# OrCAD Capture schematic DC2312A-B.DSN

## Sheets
1 PAGE3: size B; title: HIGH EFFICIENCY  DC/DC CONVERTER WITH POWER SYSTEM MANAGEMENT; rev: 2; company: TM
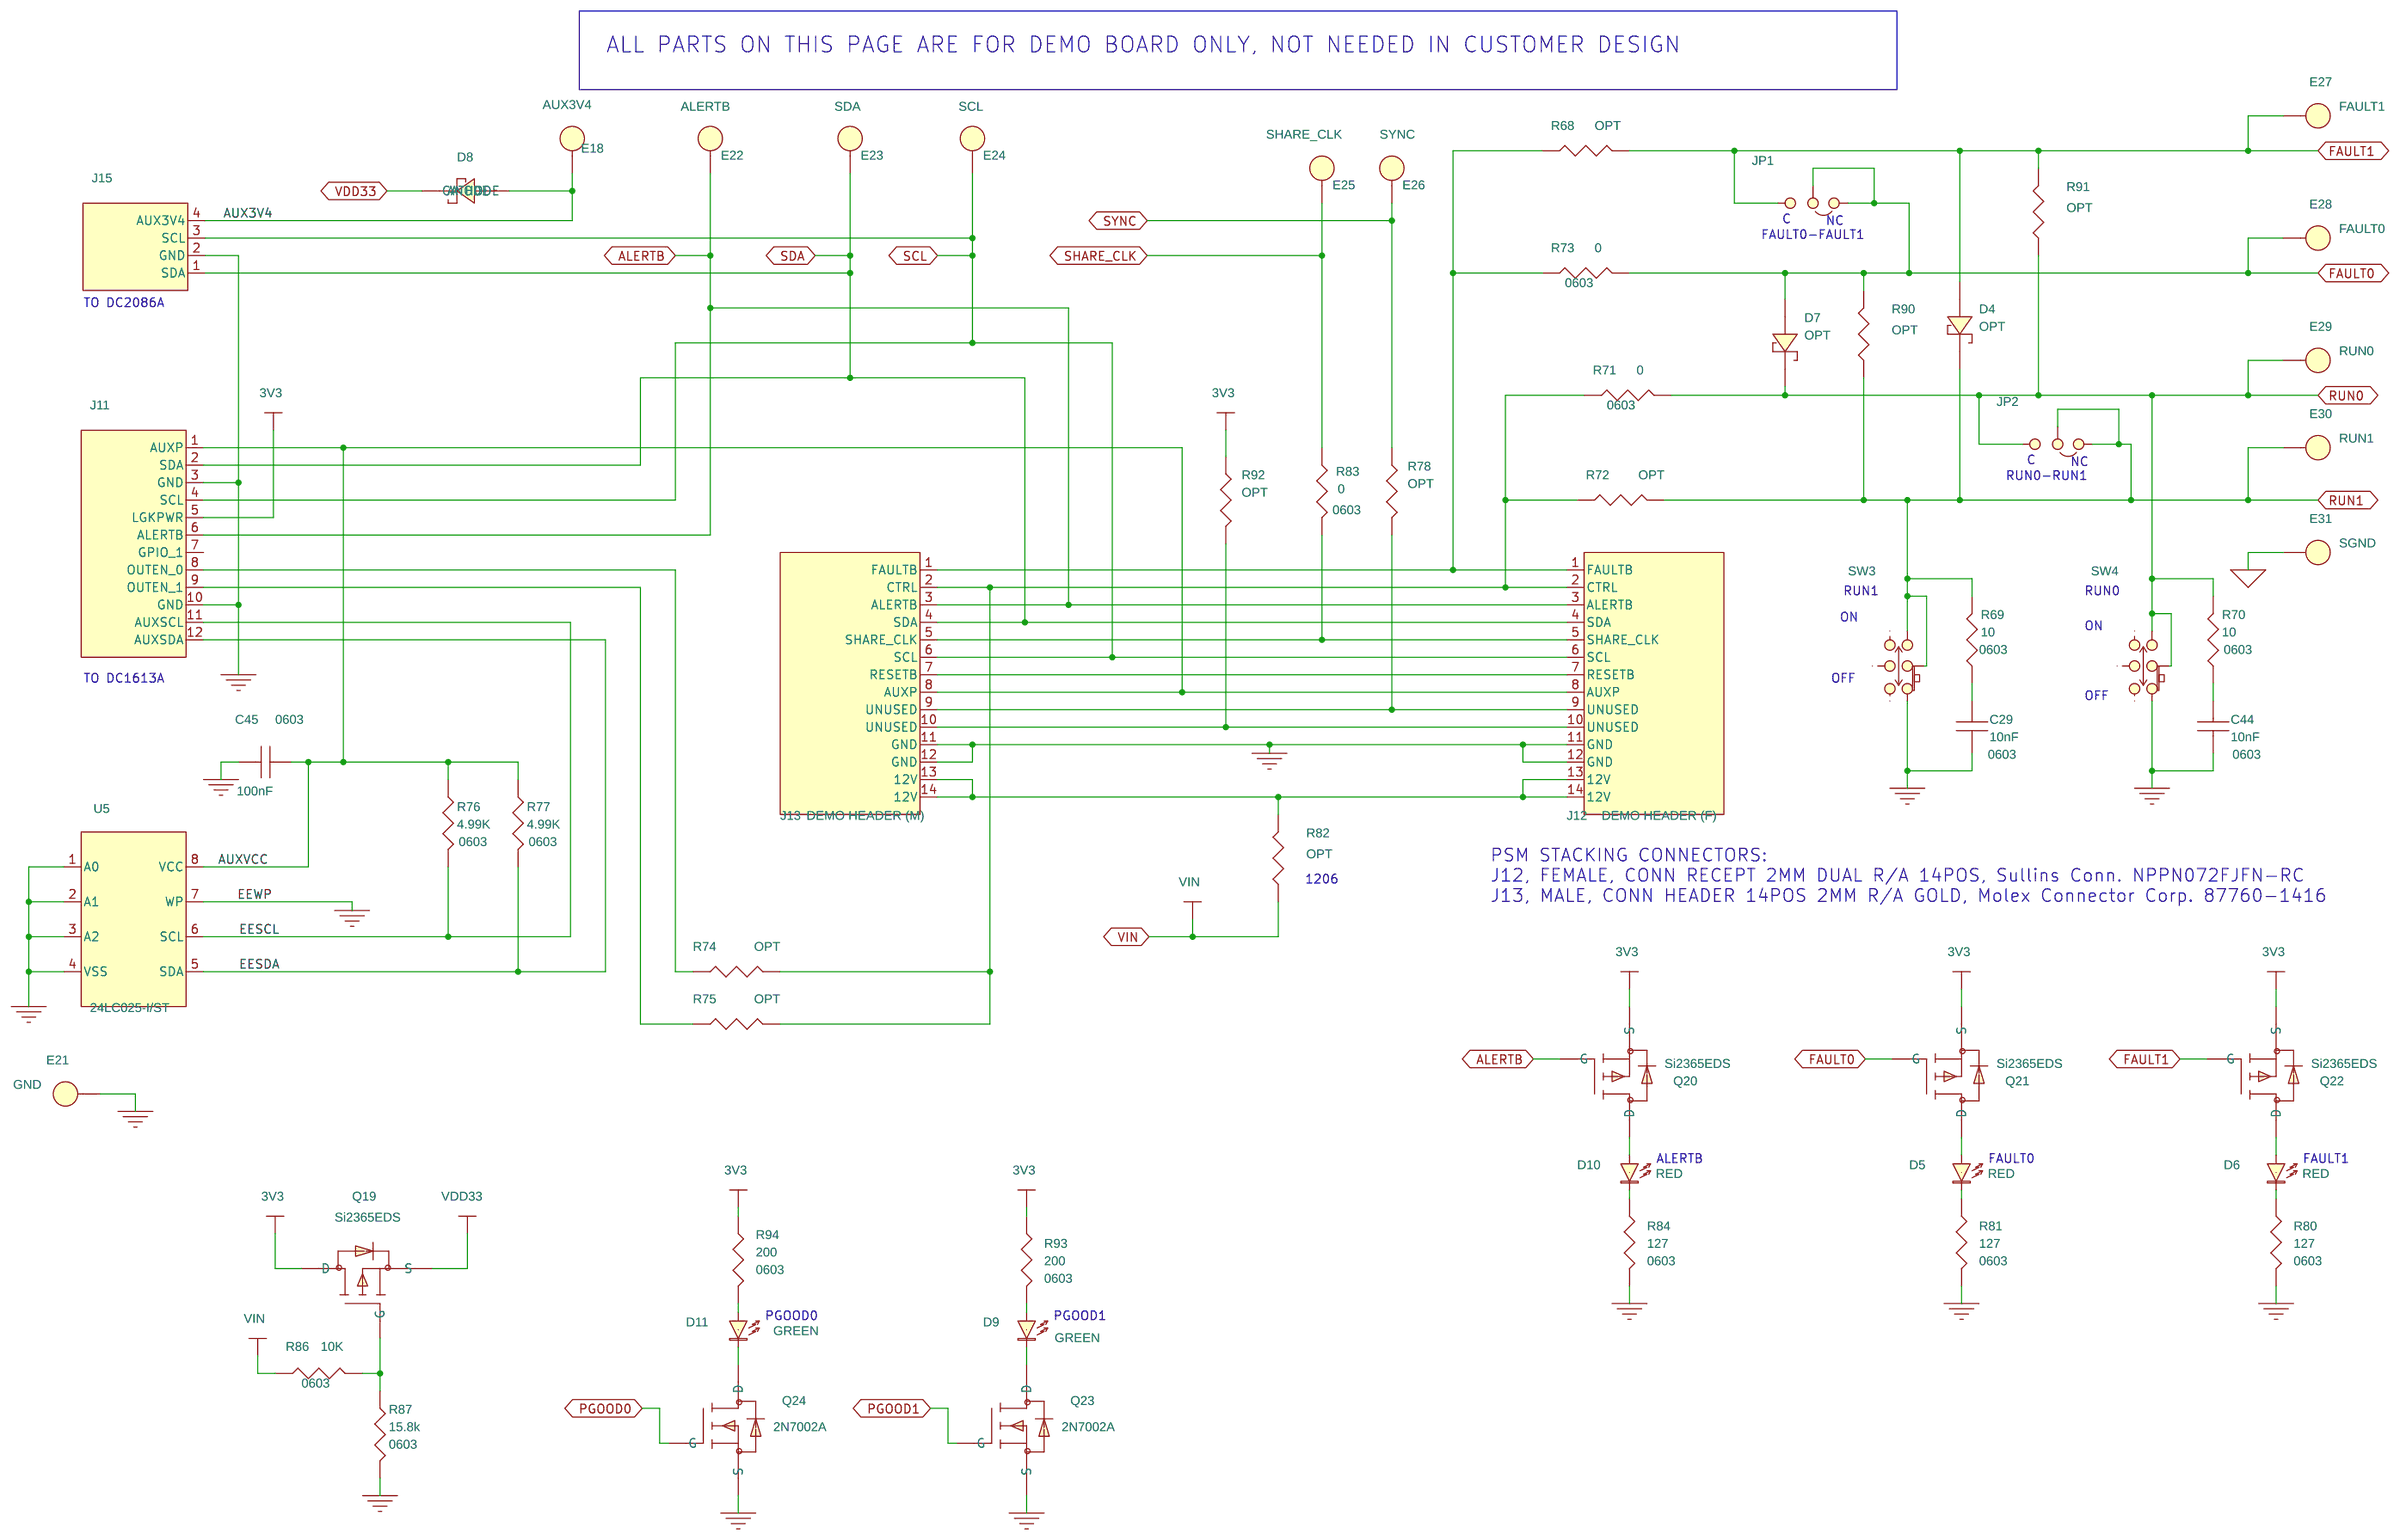
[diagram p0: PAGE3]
2 PAGE1: size Custom
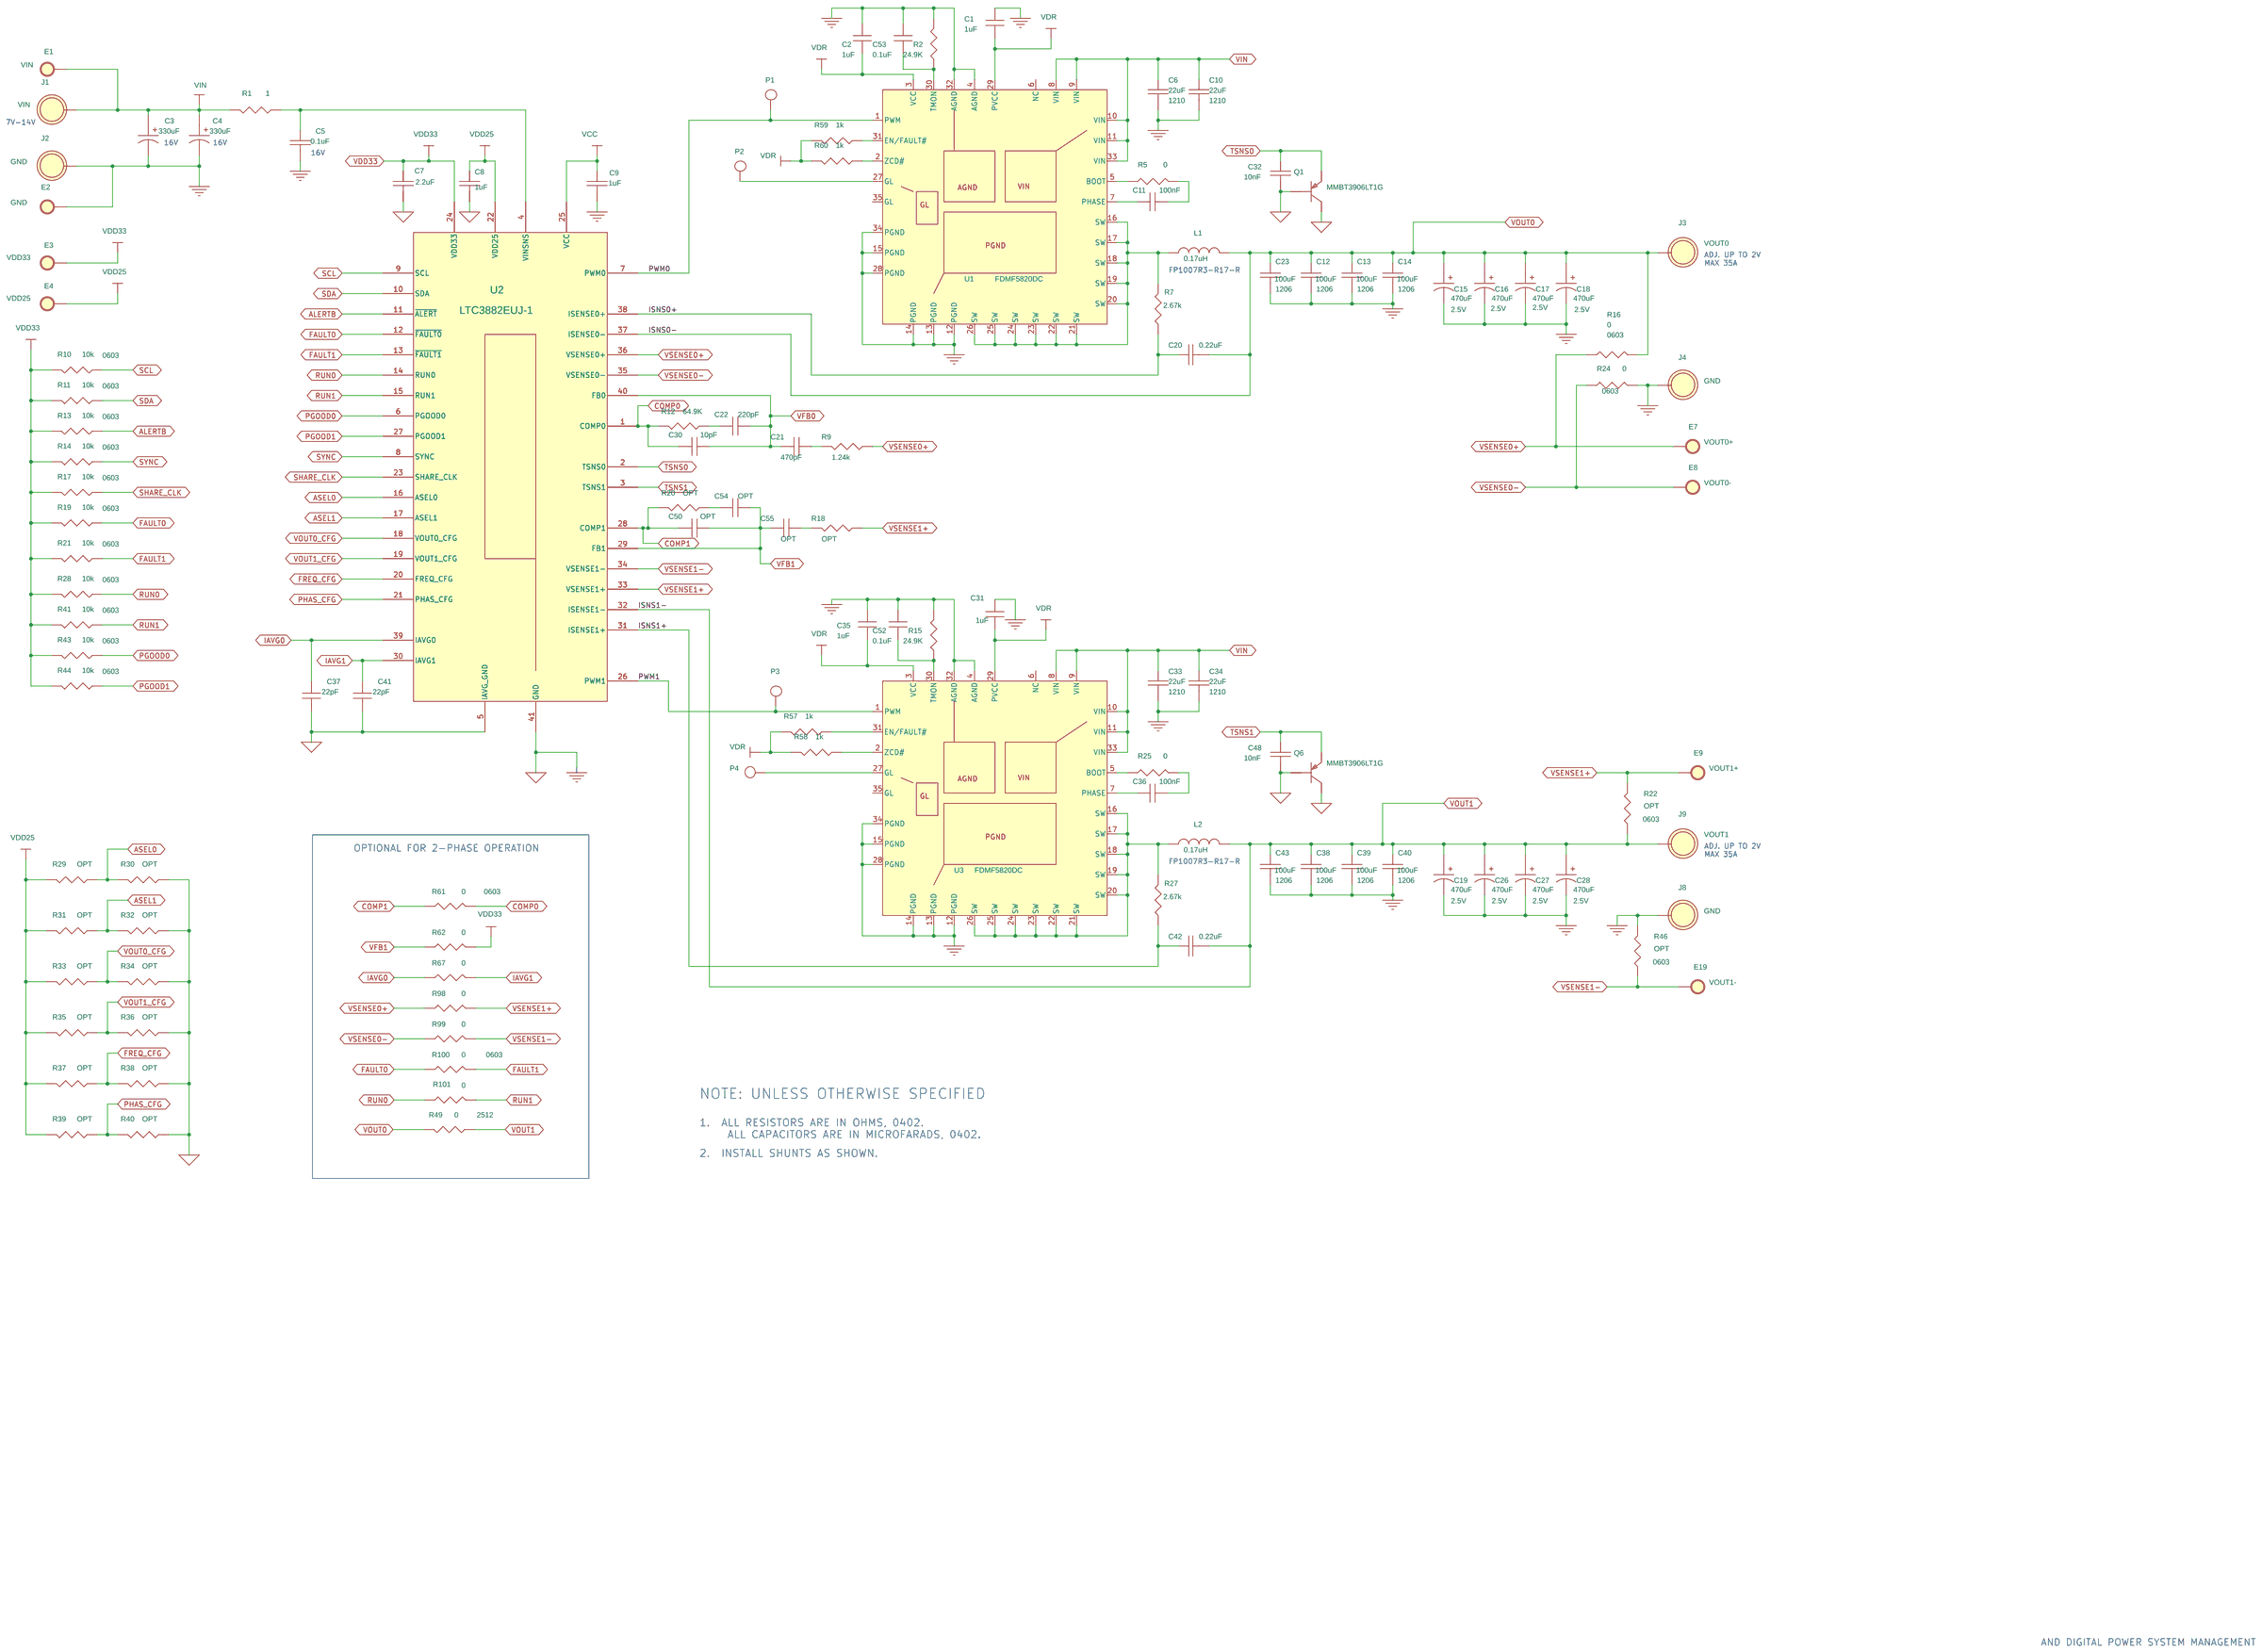
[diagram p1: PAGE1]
3 PAGE2: size Custom
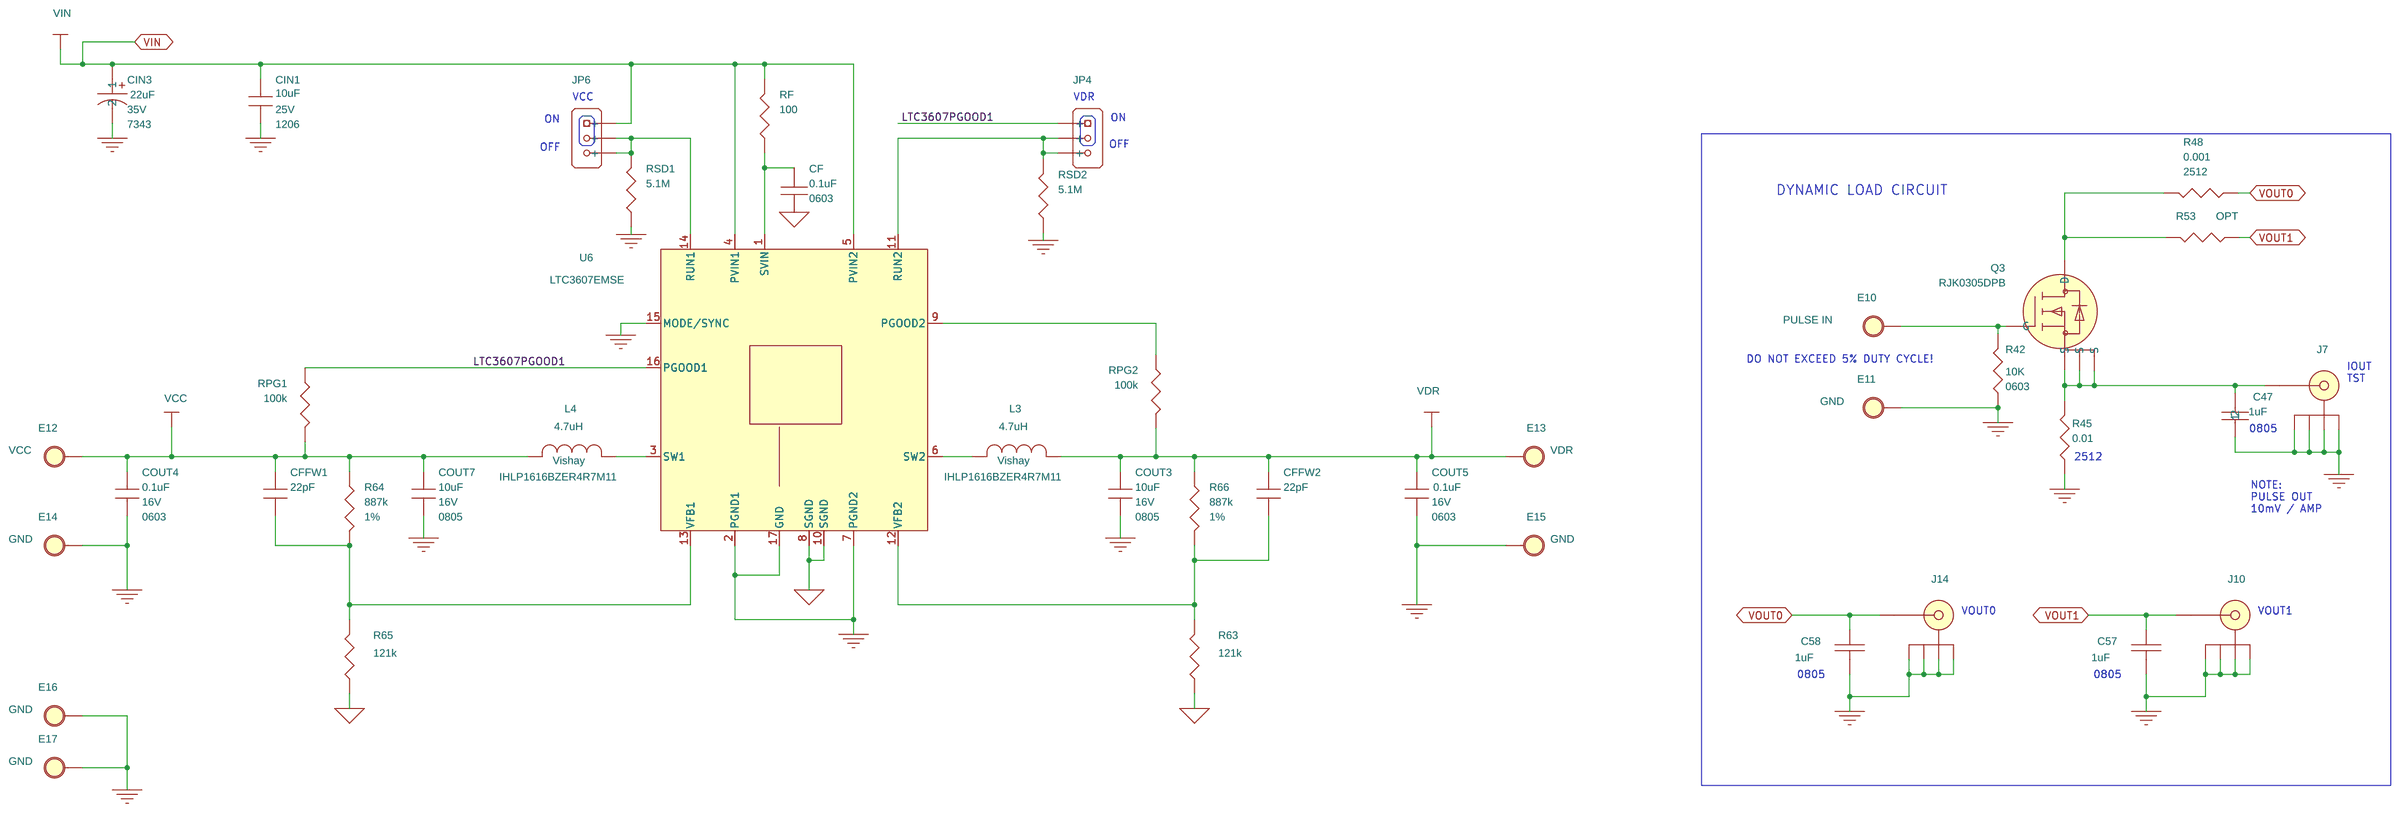
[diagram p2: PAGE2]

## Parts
sheet PAGE1
C1  1uF  [0402]
C2  1uF  [0402]
C3  330uF  [CAP_SANYO_F12]
C4  330uF  [CAP_SANYO_F12]
C5  0.1uF  [0402]
C6  22uF  [1210]
C7  2.2uF  [0402]
C8  1uF  [0402]
C9  1uF  [0402]
C10  22uF  [1210]
C11  100nF  [0402]
C12  100uF  [1206]
C13  100uF  [1206]
C14  100uF  [1206]
C15  470uF  [SANYO-C3-D2E(TPE)]
C16  470uF  [SANYO-C3-D2E(TPE)]
C17  470uF  [SANYO-C3-D2E(TPE)]
C18  470uF  [SANYO-C3-D2E(TPE)]
C19  470uF  [SANYO-C3-D2E(TPE)]
C20  0.22uF  [0402]
C21  470pF  [0402]
C22  220pF  [0402]
C23  100uF  [1206]
C26  470uF  [SANYO-C3-D2E(TPE)]
C27  470uF  [SANYO-C3-D2E(TPE)]
C28  470uF  [SANYO-C3-D2E(TPE)]
C30  10pF  [0402]
C31  1uF  [0402]
C32  10nF  [0402]
C33  22uF  [1210]
C34  22uF  [1210]
C35  1uF  [0402]
C36  100nF  [0402]
C37  22pF  [0402]
C38  100uF  [1206]
C39  100uF  [1206]
C40  100uF  [1206]
C41  22pF  [0402]
C42  0.22uF  [0402]
C43  100uF  [1206]
C48  10nF  [0402]
C50  OPT  [0402]
C52  0.1uF  [0402]
C53  0.1uF  [0402]
C54  OPT  [0402]
C55  OPT  [0402]
E1  TURRETS  [TURRETS]
E2  GND  [TURRETS]
E3  TURRETS  [TURRETS]
E4  TURRETS  [TURRETS]
E7  TURRETS  [TURRETS]
E8  TURRETS  [TURRETS]
E9  TURRETS  [TURRETS]
E19  TURRETS  [TURRETS]
J1  VIN  [KEY-575-4]
J2  GND  [KEY-575-4]
J3  VOUT0  [CON\LUG\10]
J4  GND  [CON\LUG\10]
J8  GND  [CON\LUG\10]
J9  VOUT1  [CON\LUG\10]
L1  0.17uH  [PA1320]
L2  0.17uH  [PA1320]
P1  TURRETS  [PAD]
P2  TURRETS  [PAD]
P3  TURRETS  [PAD]
P4  TURRETS  [PAD]
Q1  MMBT3906LT1G  [SOT-416]
Q6  MMBT3906LT1G  [SOT-416]
R1  1  [0402]
R2  24.9K  [0402]
R5  0  [0402]
R7  2.67k  [0402]
R9  1.24k  [0402]
R10  10k  [0603]
R11  10k  [0603]
R12  64.9K  [0402]
R13  10k  [0603]
R14  10k  [0603]
R15  24.9K  [0402]
R16  0  [0603]
R17  10k  [0603]
R18  OPT  [0402]
R19  10k  [0603]
R20  OPT  [0402]
R21  10k  [0603]
R22  OPT  [0603]
R24  0  [0603]
R25  0  [0402]
R27  2.67k  [0402]
R28  10k  [0603]
R29  OPT  [0603]
R30  OPT  [0603]
R31  OPT  [0603]
R32  OPT  [0603]
R33  OPT  [0603]
R34  OPT  [0603]
R35  OPT  [0603]
R36  OPT  [0603]
R37  OPT  [0603]
R38  OPT  [0603]
R39  OPT  [0603]
R40  OPT  [0603]
R41  10k  [0603]
R43  10k  [0603]
R44  10k  [0603]
R46  OPT  [0603]
R49  0  [2512]
R57  1k  [0402]
R58  1k  [0402]
R59  1k  [0402]
R60  1k  [0402]
R61  0  [0603]
R62  0  [0402]
R67  0  [0402]
R98  0  [0402]
R99  0  [0402]
R100  0  [0603]
R101  0  [0402]
U1  DC/DC Converters  [FDMF5821DC]
U2  LTC3882EUJ-1  [UJ-40-QFN(6X6mm)]
U3  DC/DC Converters  [FDMF5821DC]
sheet PAGE2
C47  1uF  [0805]
C57  1uF  [0805]
C58  1uF  [0805]
CF  0.1uF  [0603]
CFFW1  22pF  [0402]
CFFW2  22pF  [0402]
CIN1  10uF  [1206]
CIN3  22uF  [7343]
COUT3  10uF  [0805]
COUT4  0.1uF  [0603]
COUT5  0.1uF  [0603]
COUT7  10uF  [0805]
E10  PULSE IN  [TURRETS]
E11  GND  [TURRETS]
E12  VCC  [TURRETS]
E13  VDR  [TURRETS]
E14  GND  [TURRETS]
E15  GND  [TURRETS]
E16  GND  [TURRETS]
E17  GND  [TURRETS]
J7  XXX  [BNC]
J10  XXX  [BNC]
J14  XXX  [BNC]
JP4  ADR0  [HD1X3-079]
JP6  ADR0  [HD1X3-079]
L3  4.7uH  [INDUCTOR\IHLP-1616AB-11]
L4  4.7uH  [INDUCTOR\IHLP-1616AB-11]
Q3  RJK0305DPB  [LFPAK]
R42  10K  [0603]
R45  0.01  [2512]
R48  0.001  [2512]
R53  OPT  [2512]
R63  121k  [0402]
R64  887k  [0402]
R65  121k  [0402]
R66  887k  [0402]
RF  100  [0402]
RPG1  100k  [0402]
RPG2  100k  [0402]
RSD1  5.1M  [0402]
RSD2  5.1M  [0402]
U6  LTC3607EMSE  [MSOP-16]
sheet PAGE3
C29  10nF  [0603]
C44  10nF  [0603]
C45  100nF  [0603]
D4  OPT  [SOD-323]
D5  RED  [LED]
D6  RED  [LED]
D7  OPT  [SOD-323]
D8  DIODE SCHOTTKY  [PMEG2005AEL]
D9  GREEN  [LED]
D10  RED  [LED]
D11  GREEN  [LED]
E18  AUX3V4  [TURRETS]
E21  GND  [TURRETS]
E22  ALERTB  [TURRETS]
E23  SDA  [TURRETS]
E24  SCL  [TURRETS]
E25  SHARE_CLK  [TURRETS]
E26  SYNC  [TURRETS]
E27  FAULT1  [TURRETS]
E28  FAULT0  [TURRETS]
E29  RUN0  [TURRETS]
E30  RUN1  [TURRETS]
E31  SGND  [TURRETS]
J11  HD2X6-079  [HD2X6-079-MOLEX]
J12  DEMO HEADER (F)  [NPPN072FJFN-RC]
J13  DEMO HEADER (M)  [NPPN072FJFN]
J15  HD2X6-079-PMBUS_0  [DF3A-4P-2DSA]
JP1  JP3X1/079\NO\12  [HD1X3-079]
JP2  JP3X1/079\NO\12  [HD1X3-079]
Q19  Si2365EDS  [SOT23]
Q20  Si2365EDS  [SOT23]
Q21  Si2365EDS  [SOT23]
Q22  Si2365EDS  [SOT23]
Q23  2N7002A  [SOT-23]
Q24  2N7002A  [SOT23]
R68  OPT  [0603]
R69  10  [0603]
R70  10  [0603]
R71  0  [0603]
R72  OPT  [0603]
R73  0  [0603]
R74  OPT  [0603]
R75  OPT  [0603]
R76  4.99K  [0603]
R77  4.99K  [0603]
R78  OPT  [0603]
R80  127  [0603]
R81  127  [0603]
R82  OPT  [0603]
R83  0  [0603]
R84  127  [0603]
R86  10K  [0603]
R87  15.8k  [0603]
R90  OPT  [0603]
R91  OPT  [0603]
R92  OPT  [0603]
R93  200  [0603]
R94  200  [0603]
SW3  JP3X1/079\NO\12  [JS202011]
SW4  JP3X1/079\NO\12  [JS202011]
U5  24LC025-I/ST  [TSSOP-8_4.4MM]

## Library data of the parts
C1 C21 C30 C31 C35 C50 C52 C55 = CAP-NP: CAP, 0603 2.2uF 10% 16V X5R; Grade: X5R; Voltage rating: 16V
C2 C22 C53 C54 = CAP-NP: CAP, 0603 2.2uF 10% 16V X5R; Grade: X5R; Part Number: C0603C225K4PAC; Voltage rating: 16V
C3 C4 = CAPR12X5_0: Component: cap; Manufacturer: SANYO; Manufacturer P/N: 16SVP330M; Tolerance: 20%; Type: OS-CON; Volts/Amps/Watts: 16V
C5 = CAP_3: Manufacturer: TDK; Manufacturer P/N: C1608X7R1H104K; Tolerance: 10%; Type: cer 0603 X7R; Vendor: Digikey; Vendor P/N: 445-1314-1-ND; Volts/Amps/Watts: 50V
C6 C10 C33 C34 = CAP1210_2: Component: cap; Manufacturer: Taiyo Yuden; Manufacturer P/N: GMK325BJ106KN-T; Tolerance: 10%; Type: cer 1210; Vendor: Digikey; Vendor P/N: 587-1439-1-ND; Volts/Amps/Watts: 35V
C7 C8 = CAP_3: Manufacturer: Taiyo Yuden; Manufacturer P/N: EMK107B7105KA-T; Type: cer 0603 X7R; Vendor: Digikey; Vendor P/N: 587-1241-1-ND; Volts/Amps/Watts: 16V
C9 = CAP_4: Component: cap; Manufacturer: Taiyo Yuden; Manufacturer P/N: LMK212B7475KG-T; Tolerance: 10%; Type: cer 0805 X7R; Vendor: Digikey; Vendor P/N: 587-1442-1-ND; Volts/Amps/Watts: 10V
C11 C36 C37 C41 = EMK107BJ224MA: CAP, 0603 0.22uF 10% 25V X5R
C12-C14 C23 C38-C40 C43 = CAP_3: Component: cap; Manufacturer: TDK; Manufacturer P/N: C3225X5R0J107M; Part Type: CAP1210; Tolerance: 20%; Type: cer 1210 X5R; Vendor: Digikey; Vendor P/N: 445-1437-1-ND; Volts/Amps/Watts: 6.3v
C15-C19 C26-C28 = CAPR12X5_0: Component: cap; Manufacturer: PANASONIC; Manufacturer P/N: EEFGX0E471R; Tolerance: 20%; Type: TANT; Volts/Amps/Watts: 2.5V
C20 C42 = CAP_3: Component: cap; Manufacturer: AVX; Manufacturer P/N: 06035C102KAT2A; Tolerance: 10%; Type: cer 0603 X7R; Vendor: Digikey; Vendor P/N: 478-1215-1-ND; Volts/Amps/Watts: 50V
C32 C48 = CAP0603_1: Component: cap; Manufacturer: TDK; Manufacturer P/N: C1608X7R1H103K; Tolerance: 10%; Type: cer 0603; Vendor: Digikey; Vendor P/N: 445-1311-1-ND; Volts/Amps/Watts: 50V
E1 = TURRETS_2: Label: VIN; Manufacturer: Keystone; Manufacturer P/N: 1593-2; Vendor: Digikey; Vendor P/N: 1593-2K-ND
E2 E11 E14-E17 = TURRETS_2: Manufacturer: Keystone; Manufacturer P/N: 1593-2; Vendor: Digikey; Vendor P/N: 1593-2K-ND
E3 = TURRETS_2: Label: VDD33; Manufacturer: Keystone; Manufacturer P/N: 1593-2; Vendor: Digikey; Vendor P/N: 1593-2K-ND
E4 = TURRETS_2: Label: VDD25; Manufacturer: Keystone; Manufacturer P/N: 1593-2; Vendor: Digikey; Vendor P/N: 1593-2K-ND
E7 = TURRETS_2: Label: VOUT0+; Vendor: Digikey; Vendor P/N: 1593-2K-ND
E8 = TURRETS_2: Label: VOUT0-; Vendor: Digikey; Vendor P/N: 1593-2K-ND
E9 = TURRETS_2: Label: VOUT1+; Vendor: Digikey; Vendor P/N: 1593-2K-ND
E19 = TURRETS_2: Label: VOUT1-; Vendor: Digikey; Vendor P/N: 1593-2K-ND
J1 = E_4: STATUS: 1.6V, 1.8V, 2.0V OR 2.5V @ 15A
J2 J4 J8 = E_4: STATUS: 1.6V, 1.8V, 2.0V OR 2.5V @ 15A; VALUE2: J1
J3 J9 = E_4: VALUE2: 1V@80A
L1 L2 = 744355147_Wurth: 4th Part Field: WURTH EL.; 5th Part Field: DELTA
P1-P4 = PAD_2: Component: tp; Label: <Label>; Vendor: Digikey; Vendor P/N: 1593-2K-ND
Q1 Q6 = MMBT3906LT1_0: Component: trans; Part Type: MMBT3906LT1; Vendor P/N: MMBT3906LT1GOSCT-ND
R1 = RES0603_9: Manufacturer: Panasonic; Vendor: Digikey; Vendor P/N: P100HCT-ND; Volts/Amps/Watts: 0.1W
R2 R9 R12 R15 R18 R20 R25 = CJ06-000M: RES, 0603 0 OHM JUMPER
R5 R16 R22 R24 R46 R61 R62 R67 R98-R101 = CJ06-000M: RES, 0603 0 OHM JUMPER; Part Number: YAGEO RC0603FR-070RL
R7 R27 = RES0603_9: Manufacturer: Rohm; Manufacturer P/N: RHM0.0GCT-ND; Tolerance: 5%; Vendor: Digikey; Vendor P/N: RHM0.0GCT-ND; Volts/Amps/Watts: 0.1W
R10 R11 R13 R14 R17 R19 R21 R28-R41 R43 R44 R57-R60 = RES0603_9: Manufacturer: Panasonic; Manufacturer P/N: ERJ-3EKF2002V; Vendor: Digikey; Vendor P/N: P20.0KHCT-ND; Volts/Amps/Watts: 0.1W
R49 = RES0603_9: Label: OPT 0; Manufacturer: Rohm; Manufacturer P/N: RHM0.0GCT-ND; Tolerance: 5%; Vendor: Digikey; Vendor P/N: RHM0.0GCT-ND; Volts/Amps/Watts: 0.1W
U1 U3 = R2J20602NP(Renesas)_5: 5th Part Field: FDMF5820DC
U2 = LTC3880-M0001_20: Component: IC; Manufacturer: LTC; Manufacturer P/N: LTC3882-1; Vendor: LTC; Vendor P/N: LTC3882-1
C47 = CAP_NP_1: CAP, 0603 1.5nF 10% 50V X7R; Part Number: AVX 06033C152KAT
C57 C58 = CAP1206_1: Manufacturer: Kemet; Manufacturer P/N: C1206C106K8RACTU; Tolerance: 10%; Type: cer 1206 X7R; Vendor: Digikey; Vendor P/N: 399-4937-1-ND; Volts/Amps/Watts: 10V
CF = 04023A102KAT2A
CFFW1 CFFW2 = CAP1210: 1ST PART FIELD: 25V; 2ND PART FIELD: 20%; 3RD PART FIELD: COG
CIN1 = CAP1206: 1ST PART FIELD: 25V
CIN3 = CAPACITOR_POL: Voltage: 35V
COUT3 COUT7 = CAP1210: 1ST PART FIELD: 16V
COUT4 COUT5 = CAP0805: 1ST PART FIELD: 16V
E10 E12 E13 = TURRETS_2: Label: GND; Manufacturer: Keystone; Manufacturer P/N: 1593-2; Vendor: Digikey; Vendor P/N: 1593-2K-ND
J7 J10 J14 = BNC5-SCH_0: CONN,BNC,5 PINS; Part Number: CONNEX 112404
JP4 JP6 = CON6AP_4
L3 L4 = D53LC: 4TH PART FIELD: Vishay; 5TH PART FIELD: IHLP1616BZER4R7M11
Q3 = MOS_FET_5: XSTR, N-CHANNEL DMOS FET
R42 = RES0603_9
R45 R48 R53 = RES0603_5: Label: 1W; Manufacturer: VISHAY; Manufacturer P/N: CRCW251230R0JNEG; Tolerance: 5%; Vendor: Digikey; Vendor P/N: 541-30XCT-ND; Volts/Amps/Watts: 0.1W
R63 R65 = CR05-3923FM
R64 R66 = CR05-104JM: 2nd Part Field: 1%
RF = CR05-1502FM: 2nd Part Field: 5%
RPG1 RPG2 RSD1 RSD2 = CR05-104JM
U6 = LTC3607EMSEMOD1_0
C29 C44 = CAP_NP: CAP, 0603 10nF 10% 25V X7R; Part Number: AVX 06033C103KAT2A
C45 = CAP_NP: CAP, 0603 100nF 20% 16V X7R; Part Number: AVX 0603YC104MAT2A
D4 D7 = DIODE_SCHOTTKY_9: DIODE, SCHOTTKY 30V, 100mA; Part Number: CENTRAL SEMI CMDSH-3-TR
D5 D6 D10 = DIODE-LED_2: LED, 0603 RED; Label: GREEN; Manufacturer: PANASONIC; Part Number: WURTH ELEKTRONIK 150060SS75000
D8 = DIODE_SCHOTTKY_0
D9 D11 = DIODE-LED_2: LED, 0603 GREEN; Manufacturer: PANASONIC; Manufacturer P/N: LN1371SGTRP; Part Number: WURTH ELEKTRONIK 150060GS75000
E18 E21-E31 = E_0: TURRET; Part Number: MILL MAX 2501-2-00-80-00-00-07-0
J11 = HD2X6-079-PMBUS_2: HEADER, 12PIN 2mm STR DL; Label: DC1427A HEADER; Manufacturer: MOLEX; Manufacturer P/N: 87831-1220; Part Number: FCI 98414-G06-12ULF; Type: header 12POS 2MM VERT; Vendor: Digikey; Vendor P/N: WM18561-ND
J12 = PMBUS_CONNECTOR20_3: CONN, SOCKET 20PIN  DUAL ROW R/A; Component: con; Manufacturer: Mill Max; Manufacturer P/N: 803-93-020-20-001; Part Number: MILL MAX 803-93-020-20-001; Part Type: HDR2X10RA; Type: conn  RA 20 dual row; Vendor: LTC; Vendor P/N: 803-93-020-20-001
J13 = PMBUS_HEADER20_3: HEADER, 20PIN DUAL ROW R/A; Component: con; Manufacturer: Mill Max; Manufacturer P/N: 802-40-020-20-0001; Part Number: MILL MAX 802-40-020-20-0001; Part Type: HDR_2X10_RA_REV; Type: header RA 20 dual row; Vendor: LTC; Vendor P/N: 802-40-020-20-001
J15 = HD2X6-079-PMBUS_4: HEADER, 4PIN 2mm STR DL; Manufacturer: Hirose; Type: header 4POS 2MM VERT
JP1 JP2 = JP3X1_079_NO_12_2
Q19-Q22 = P-MOSFET: XSTR, N-CHANNEL DMOS FET; Part Number: VISHAY Si2365EDS
Q23 = TRANSISTOR_1: XSTR, N-CHANNEL DMOS FET; Part Number: FAIRCHILD 2N7002A
Q24 = TRANSISTOR_0: XSTR, N-CHANNEL DMOS FET; Part Number: FAIRCHILD 2N7002A
R68 R71-R73 = RES0603_0: RES, 0603 0 OHMS JUMPER; Label: OPT 0; Manufacturer: Rohm; Manufacturer P/N: RHM0.0GCT-ND; Part Number: VISHAY CRCW06030000Z0EA; Tolerance: 5%; Vendor: Digikey; Vendor P/N: RHM0.0GCT-ND; Volts/Amps/Watts: 0.1W
R69 R70 = RES0603_1: RES, 0603 10 OHMS 5% 1/10W; Manufacturer: Rohm; Manufacturer P/N: RHM0.0GCT-ND; Part Number: VISHAY CRCW060310R0JNEA; Tolerance: 5%; Vendor: Digikey; Vendor P/N: RHM0.0GCT-ND; Volts/Amps/Watts: 0.1W
R74 R82 = RES0603_3: RES, 0603 OPTION; Label: OPT 0; Manufacturer: Rohm; Manufacturer P/N: RHM0.0GCT-ND; Part Number: OPTION; Tolerance: 5%; Vendor: Digikey; Vendor P/N: RHM0.0GCT-ND; Volts/Amps/Watts: 0.1W
R75 R78 R90-R92 = RES0603_0: RES, 0603 OPTION; Label: OPT 0; Manufacturer: Rohm; Manufacturer P/N: RHM0.0GCT-ND; Part Number: OPTION; Tolerance: 5%; Vendor: Digikey; Vendor P/N: RHM0.0GCT-ND; Volts/Amps/Watts: 0.1W
R76 R77 = RES0603_0: RES, 0603 4.99K OHMS 1% 1/10W; Manufacturer: ROHM; Manufacturer P/N: MCR03EZPFX4991; Part Number: VISHAY CRCW06034K99FKEA; Vendor: Digikey; Vendor P/N: RHM4.99KHCT-ND; Volts/Amps/Watts: 0.1w
R80 R81 R84 = RES0603_0: RES, 0603 127 OHMS 1% 1/10W; Label: OPT 0; Manufacturer: Rohm; Manufacturer P/N: RHM0.0GCT-ND; Part Number: VISHAY CRCW0603127RFKEA; Tolerance: 5%; Vendor: Digikey; Vendor P/N: RHM0.0GCT-ND; Volts/Amps/Watts: 0.1W
R83 = RES0603_0: RES, 0603 0 OHMS JUMPER; Manufacturer: Rohm; Manufacturer P/N: RHM0.0GCT-ND; Part Number: VISHAY CRCW06030000Z0EA; Tolerance: 5%; Vendor: Digikey; Vendor P/N: RHM0.0GCT-ND; Volts/Amps/Watts: 0.1W
R86 = RES0603_11: RES, 0603 10K OHMS 5% 1/10W; Part Number: VISHAY CRCW060310K0JNEA
R87 = RES0603_11: RES, 0603 15.8K OHMS 1% 1/10W; Part Number: VISHAY CRCW060315K8FKEA
R93 R94 = RES0603_0: RES, 0603 200 OHMS 5% 1/10W; Label: OPT 0; Manufacturer: Rohm; Manufacturer P/N: RHM0.0GCT-ND; Part Number: VISHAY CRCW0603200RJNEA; Tolerance: 5%; Vendor: Digikey; Vendor P/N: RHM0.0GCT-ND; Volts/Amps/Watts: 0.1W
SW3 SW4 = JP3X1_079_NO_12_3: SWITCH, SUBMINATURE SLIDE; Part Number: C&K JS202011CQN
U5 = 24LC025-I_SN: IC, 24LC05-I/ST; Part Number: MICROCHIP 24LC025-I/ST

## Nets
3V3: J11.5(LGKPWR) Q19.3(D) Q20.2(S) Q21.2(S) Q22.2(S) R92.1 R93.1 R94.1
GND_POWER: C1.1 C2.1 C3.2 C4.2 C5.2 C6.2 C9.2 C10.2 C12.2 C13.2 C14.2 C15.2 C16.2 C17.2 C18.2 C19.2 C23.2 C26.2 C27.2 C28.2 C29.2 C31.1 C33.2 C34.2 C35.1 C38.2 C39.2 C40.2 C43.2 C44.2 C45.2 C47.1 C52.1 C53.1 C57.2 C58.2 CIN1.2 CIN3.2 COUT3.2 COUT4.2 COUT5.2 COUT7.2 E2.1(TP) E11.1(TP) E14.1(TP) E15.1(TP) E16.1(TP) E17.1(TP) E21.1(A) J2.1(A) J4.1(A) J7.2 J7.3 J7.4 J7.5 J8.1(A) J10.2 J10.3 J10.4 J10.5 J11.3(GND) J11.10(GND) J12.11(GND) J12.12(GND) J13.11(GND) J13.12(GND) J14.2 J14.3 J14.4 J14.5 J15.2(GND) Q23.2(S) Q24.2(S) R2.1 R15.1 R24.1 R42.2 R45.1 R46.1 R80.2 R81.2 R84.2 R87.2 RSD1.1 RSD2.1 SW3.3 SW4.3 U1.4(AGND) U1.12(PGND) U1.13(PGND) U1.14(PGND) U1.15(PGND) U1.28(PGND) U1.32(AGND) U1.34(PGND) U3.4(AGND) U3.12(PGND) U3.13(PGND) U3.14(PGND) U3.15(PGND) U3.28(PGND) U3.32(AGND) U3.34(PGND) U5.1(A0) U5.2(A1) U5.3(A2) U5.4(VSS) U5.7(WP) U6.2(PGND1) U6.7(PGND2) U6.15(MODE/SYNC) U6.17(GND)
GND_SIGNAL: C7.2 C8.2 C32.2 C37.2 C41.2 C48.2 CF.1 E31.1(A) Q1.1(BASE) Q1.3(COLLECTOR) Q6.1(BASE) Q6.3(COLLECTOR) R30.1 R32.1 R34.1 R36.1 R38.1 R40.1 R63.1 R65.1 U2.5(IAVG_GND) U2.41(GND) U6.8(SGND) U6.10(SGND)
VCC: C9.1 CFFW1.1 COUT4.1 COUT7.1 E12.1(TP) L4.1 R64.1 RPG1.2 U2.25(VCC)
VDD25: C8.1 E4.1(TP) R29.2 R31.2 R33.2 R35.2 R37.2 R39.2 U2.22(VDD25)
VDD33: C7.1 D8.1(CATHODE) E3.1(TP) Q19.2(S) R10.2 R11.2 R13.2 R14.2 R17.2 R19.2 R21.2 R28.2 R41.2 R43.2 R44.2 R62.1 U2.24(VDD33)
VIN: C3.1 C4.1 C6.1 C10.1 C33.1 C34.1 CIN1.1 CIN3.1 E1.1(TP) J1.1(A) JP6.1(+) R1.1 R82.1 R86.1 RF.1 U1.8(VIN) U1.9(VIN) U1.10(VIN) U1.11(VIN) U1.33(VIN) U3.8(VIN) U3.9(VIN) U3.10(VIN) U3.11(VIN) U3.33(VIN) U6.4(PVIN1) U6.5(PVIN2)
ALERTB: E22.1(A) J11.6(ALERTB) J12.3(ALERTB) J13.3(ALERTB) Q20.1(G) R13.1 U2.11(~{ALERT})
ASEL0: R29.1 R30.2 U2.16(ASEL0)
ASEL1: R31.1 R32.2 U2.17(ASEL1)
AUX3V4: D8.2(ANODE) E18.1(A) J15.4(AUX3V4)
AUXVCC: C45.1 J11.1(AUXP) J12.8(AUXP) J13.8(AUXP) R76.1 R77.1 U5.8(VCC)
COMP0: C30.2 R12.1 R61.1 U2.1(COMP0)
COMP1: C50.2 R20.1 R61.2 U2.28(COMP1)
EESCL: J11.11(AUXSCL) R76.2 U5.6(SCL)
EESDA: J11.12(AUXSDA) R77.2 U5.5(SDA)
FAULT0: D7.2(ANODE) E28.1(A) JP1.1 JP1.2 Q21.1(G) R19.1 R73.2 R90.2 R100.2 U2.12(~{FAULT0})
FAULT1: D4.2(ANODE) E27.1(A) JP1.3 Q22.1(G) R21.1 R68.2 R91.2 R100.1 U2.13(~{FAULT1})
FREQ_CFG: R37.1 R38.2 U2.20(FREQ_CFG)
IAVG0: C37.1 R67.2 U2.39(IAVG0)
IAVG1: C41.1 R67.1 U2.30(IAVG1)
ISNS0+: C20.1 R7.1 U2.38(ISENSE0+)
ISNS1+: C42.1 R27.1 U2.31(ISENSE1+)
LTC3607PGOOD1: JP4.1(+) RPG1.1 U6.16(PGOOD1)
PGOOD0: Q24.1(G) R43.1 U2.6(PGOOD0)
PGOOD1: Q23.1(G) R44.1 U2.27(PGOOD1)
PHAS_CFG: R39.1 R40.2 U2.21(PHAS_CFG)
PWM0: P1.1(TP) U1.1(PWM) U2.7(PWM0)
PWM1: P3.1(TP) U2.26(PWM1) U3.1(PWM)
RUN0: D7.1(CATHODE) E29.1(A) JP2.3 R28.1 R70.2 R71.2 R91.1 R101.2 SW4.1 SW4.2 U2.14(RUN0)
RUN1: D4.1(CATHODE) E30.1(A) JP2.1 JP2.2 R41.1 R69.2 R72.2 R90.1 R101.1 SW3.1 SW3.2 U2.15(RUN1)
SCL: E24.1(A) J11.4(SCL) J12.6(SCL) J13.6(SCL) J15.3(SCL) R10.1 U2.9(SCL)
SDA: E23.1(A) J11.2(SDA) J12.4(SDA) J13.4(SDA) J15.1(SDA) R11.1 U2.10(SDA)
SHARE_CLK: E25.1(A) R17.1 R83.1 U2.23(SHARE_CLK)
SYNC: E26.1(A) R14.1 R78.1 U2.8(SYNC)
TSNS0: C32.1 Q1.2(EMITTER) U2.2(TSNS0)
TSNS1: C48.1 Q6.2(EMITTER) U2.3(TSNS1)
VDR: C1.2 C2.2 C31.2 C35.2 CFFW2.1 COUT3.1 COUT5.1 E13.1(TP) L3.2 R57.2 R58.2 R59.2 R60.2 R66.1 RPG2.2 U1.3(VCC) U1.29(PVCC) U3.3(VCC) U3.29(PVCC)
VFB0: C21.2 C22.1 C30.1 U2.40(FB0)
VFB1: C50.1 C54.1 C55.2 R62.2 U2.29(FB1)
VOUT0: C12.1 C13.1 C14.1 C15.1 C16.1 C17.1 C18.1 C20.2 C23.1 C58.1 J3.1(A) J14.1 L1.2 R16.1 R48.1 R49.2 U2.37(ISENSE0-)
VOUT0_CFG: R33.1 R34.2 U2.18(VOUT0_CFG)
VOUT1: C19.1 C26.1 C27.1 C28.1 C38.1 C39.1 C40.1 C42.2 C43.1 C57.1 J9.1(A) J10.1 L2.2 R22.2 R49.1 R53.1 U2.32(ISENSE1-)
VOUT1_CFG: R35.1 R36.2 U2.19(VOUT1_CFG)
VSENSE0+: E7.1(TP) R9.2 R16.2 R98.2 U2.36(VSENSE0+)
VSENSE0-: E8.1(TP) R24.2 R99.2 U2.35(VSENSE0-)
VSENSE1+: E9.1(TP) R18.2 R22.1 R98.1 U2.33(VSENSE1+)
VSENSE1-: E19.1(TP) R46.2 R99.1 U2.34(VSENSE1-)
N23714908: C5.1 R1.2 U2.4(VINSNS)
N23716348: L1.1 R7.2 U1.16(SW) U1.17(SW) U1.18(SW) U1.19(SW) U1.20(SW) U1.21(SW) U1.22(SW) U1.23(SW) U1.24(SW) U1.25(SW) U1.26(SW)
N23719885: C47.2 J7.1 Q3.1(S) Q3.2(S) Q3.3(S) R45.2
N23719907: Q3.5(D) R48.2 R53.2
N23720351: E10.1(TP) Q3.4(G) R42.1
N24021185: C22.2 R12.2
N24250445: R5.2 U1.5(BOOT)
N24253641: C11.1 U1.7(PHASE)
N24261598: C11.2 R5.1
N24287614: C53.2 R2.2 U1.30(TMON)
N24331714: L2.1 R27.2 U3.16(SW) U3.17(SW) U3.18(SW) U3.19(SW) U3.20(SW) U3.21(SW) U3.22(SW) U3.23(SW) U3.24(SW) U3.25(SW) U3.26(SW)
N24331908: C36.2 R25.1
N24331914: C52.2 R15.2 U3.30(TMON)
N24331960: R25.2 U3.5(BOOT)
N24332030: C36.1 U3.7(PHASE)
N24914620: R57.1 U3.31(EN/FAULT#)
N24926898: R58.1 U3.2(ZCD#)
N24933358: R59.1 U1.31(EN/FAULT#)
N24937896: R60.1 U1.2(ZCD#)
N25245360: C21.1 R9.1
N25253737: C54.2 R20.2
N25261019: C55.1 R18.1
N25442827: J12.1(FAULTB) J13.1(FAULTB) R68.1 R73.1
N25442922: J12.2(CTRL) J13.2(CTRL) R71.1 R72.1 R74.2 R75.2
N25442990: J12.5(SHARE_CLK) J13.5(SHARE_CLK) R83.2
N25443001: J12.7(RESETB) J13.7(RESETB)
N25443007: J12.9(UNUSED) J13.9(UNUSED) R78.2
N25443112: J11.8(OUTEN_0) R74.1
N25443342: J12.13(12V) J12.14(12V) J13.13(12V) J13.14(12V) R82.2
N25443514: J11.9(OUTEN_1) R75.1
N25443624: D10.2(A) Q20.3(D)
N25443643: D10.1(K) R84.1
N25443783: Q19.1(G) R86.2 R87.1
N25443886: C29.1 R69.1
N25443903: J12.10(UNUSED) J13.10(UNUSED) R92.2
N25443911: C44.1 R70.1
N25656498: P2.1(TP) U1.27(GL)
N25667422: P4.1(TP) U3.27(GL)
N25952860: D11.2(A) R94.2
N25952862: D11.1(K) Q24.3(D)
N25952876: D9.1(K) Q23.3(D)
N25952958: D9.2(A) R93.2
N26014451: D5.2(A) Q21.3(D)
N26014459: D5.1(K) R81.1
N26017515: D6.2(A) Q22.3(D)
N26017519: D6.1(K) R80.1
N26098508: RPG2.1 U6.9(PGOOD2)
N26098523: L4.2 U6.3(SW1)
N26098529: CF.2 RF.2 U6.1(SVIN)
N26098554: JP6.2(+) JP6.3(+) RSD1.2 U6.14(RUN1)
N26098562: CFFW2.2 R63.2 R66.2 U6.12(VFB2)
N26098622: JP4.2(+) JP4.3(+) RSD2.2 U6.11(RUN2)
N26098674: CFFW1.2 R64.2 R65.2 U6.13(VFB1)
N26098846: L3.1 U6.6(SW2)

Not connected (* = marked no-connect by the designer): J11 7(GPIO_1); SW3 4 5 6; SW4 4 5 6; U1 6(NC) 35(GL); U3 6(NC) 35(GL)

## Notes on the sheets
sheet 1
- ALL PARTS ON THIS PAGE ARE FOR DEMO BOARD ONLY, NOT NEEDED IN CUSTOMER DESIGN
- C
- NC
- FAULT0-FAULT1
- TO DC2086A
- RUN0-RUN1
- C
- NC
- RUN1
- RUN0
- ON
- ON
- TO DC1613A
- OFF
- OFF
- PSM STACKING CONNECTORS:
  J12, FEMALE, CONN RECEPT 2MM DUAL R/A 14POS, Sullins Conn. NPPN072FJFN-RC
  J13, MALE, CONN HEADER 14POS 2MM R/A GOLD, Molex Connector Corp. 87760-1416
- 1206
- ALERTB
- FAULT0
- FAULT1
- PGOOD0
- PGOOD1
sheet 2
- 7V-14V
- 16V
- 16V
- 16V
- ADJ. UP TO 2V
  MAX 35A
- FP1007R3-R17-R
- OPTIONAL FOR 2-PHASE OPERATION
- ADJ. UP TO 2V
  MAX 35A
- FP1007R3-R17-R
- NOTE: UNLESS OTHERWISE SPECIFIED
- 1.  ALL RESISTORS ARE IN OHMS, 0402.
       ALL CAPACITORS ARE IN MICROFARADS, 0402.
- 2.  INSTALL SHUNTS AS SHOWN.
- AND DIGITAL POWER SYSTEM MANAGEMENT
sheet 3
- VCC
- VDR
- ON
- ON
- OFF
- OFF
- DYNAMIC LOAD CIRCUIT
- DO NOT EXCEED 5% DUTY CYCLE!
- IOUT
  TST
- 0805
- 2512
- NOTE:
  PULSE OUT
  10mV / AMP
- VOUT0
- VOUT1
- 0805
- 0805
